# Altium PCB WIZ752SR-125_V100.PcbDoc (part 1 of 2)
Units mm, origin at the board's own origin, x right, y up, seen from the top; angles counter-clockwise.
Board outline 60 x 85 mm, 4 copper layers (Top Layer, Internal Plane 1, Internal Plane 2, Bottom Layer); 105 components, 107 nets, 391 pads, 152 vias.
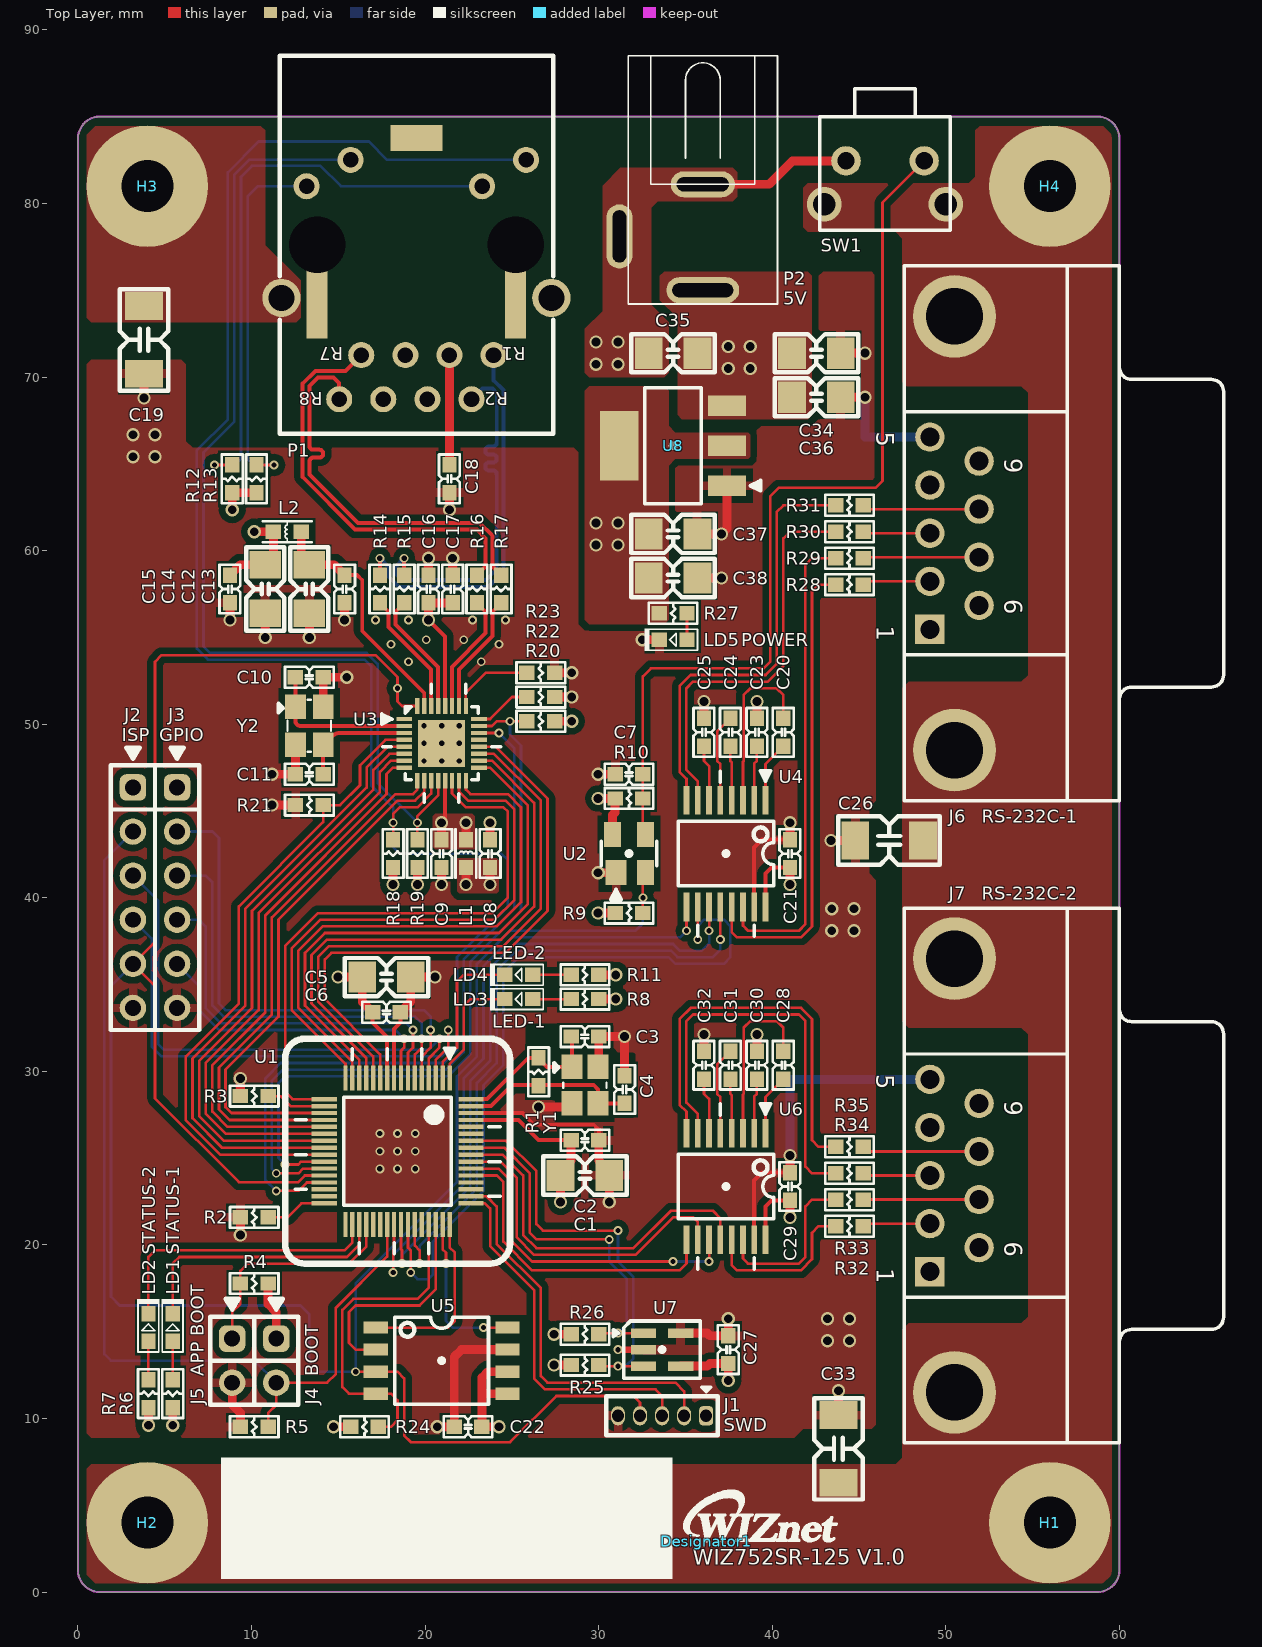
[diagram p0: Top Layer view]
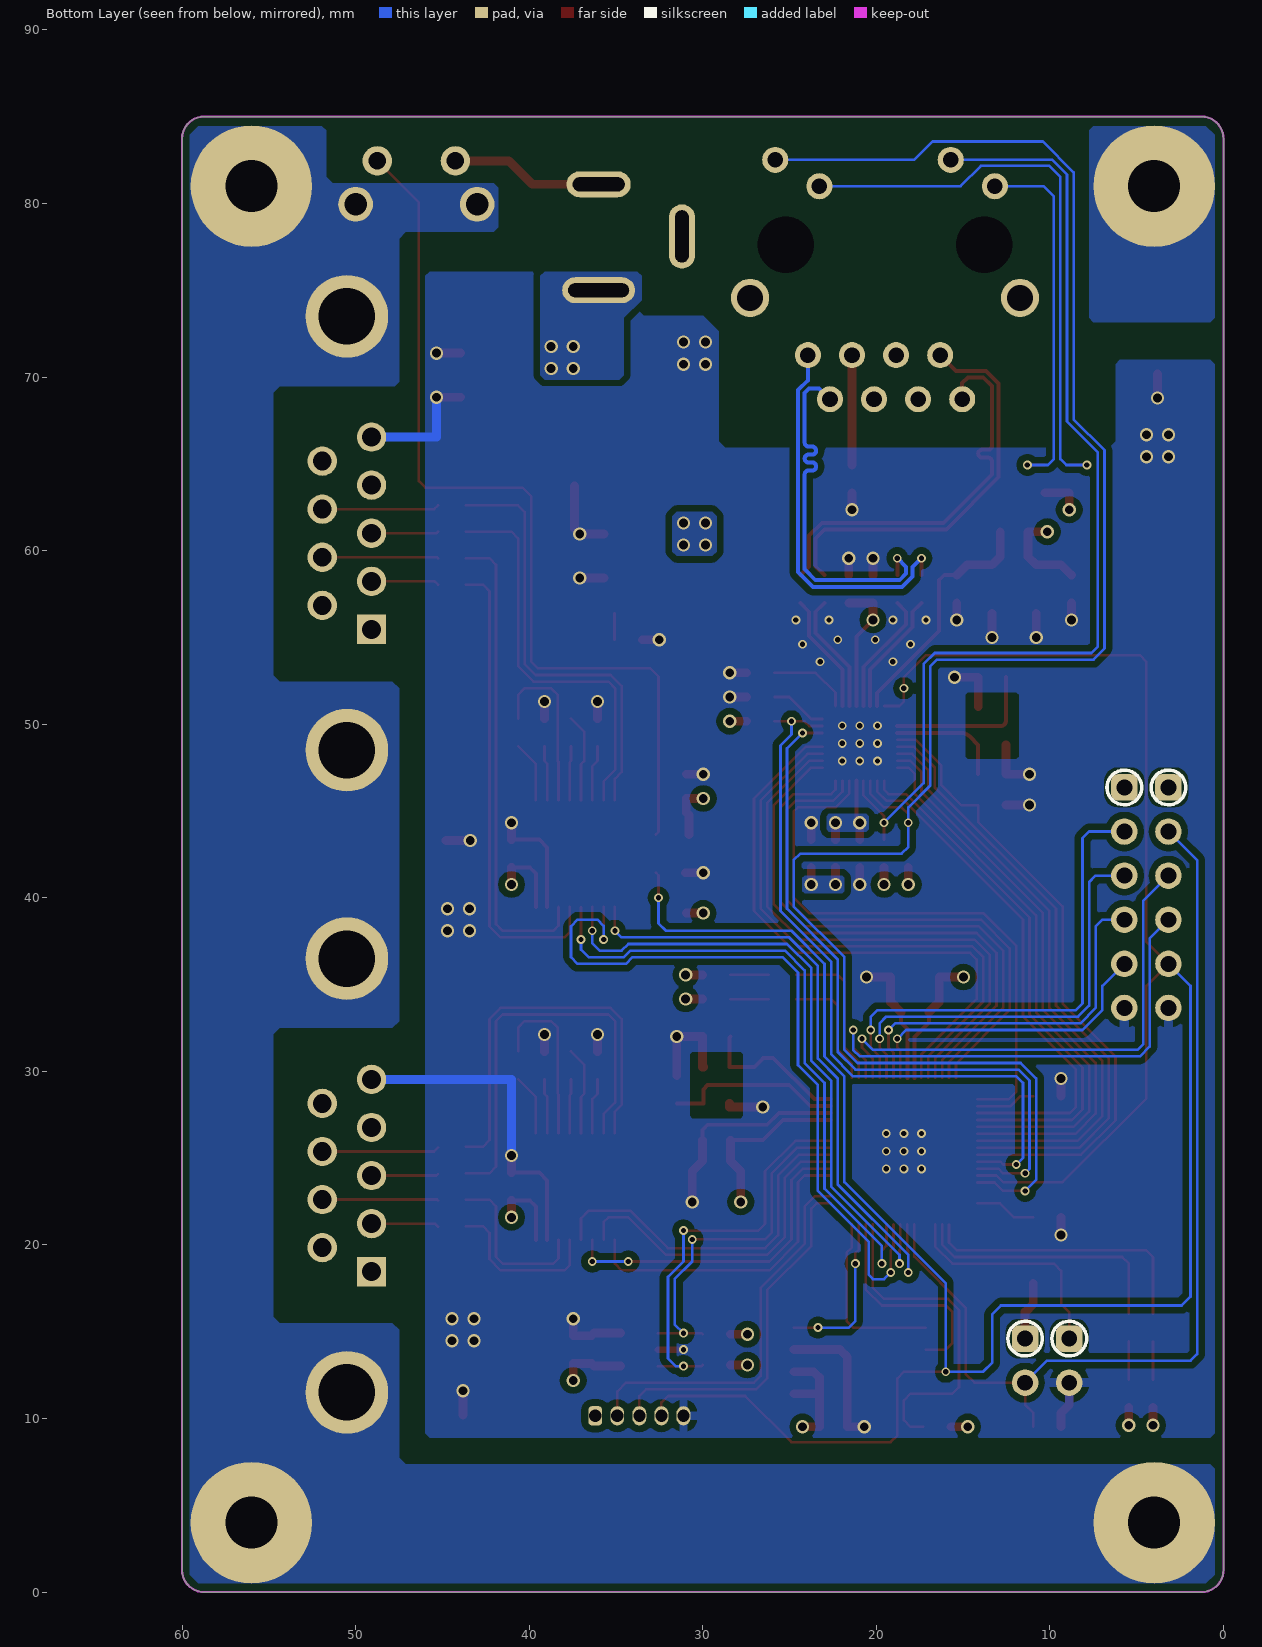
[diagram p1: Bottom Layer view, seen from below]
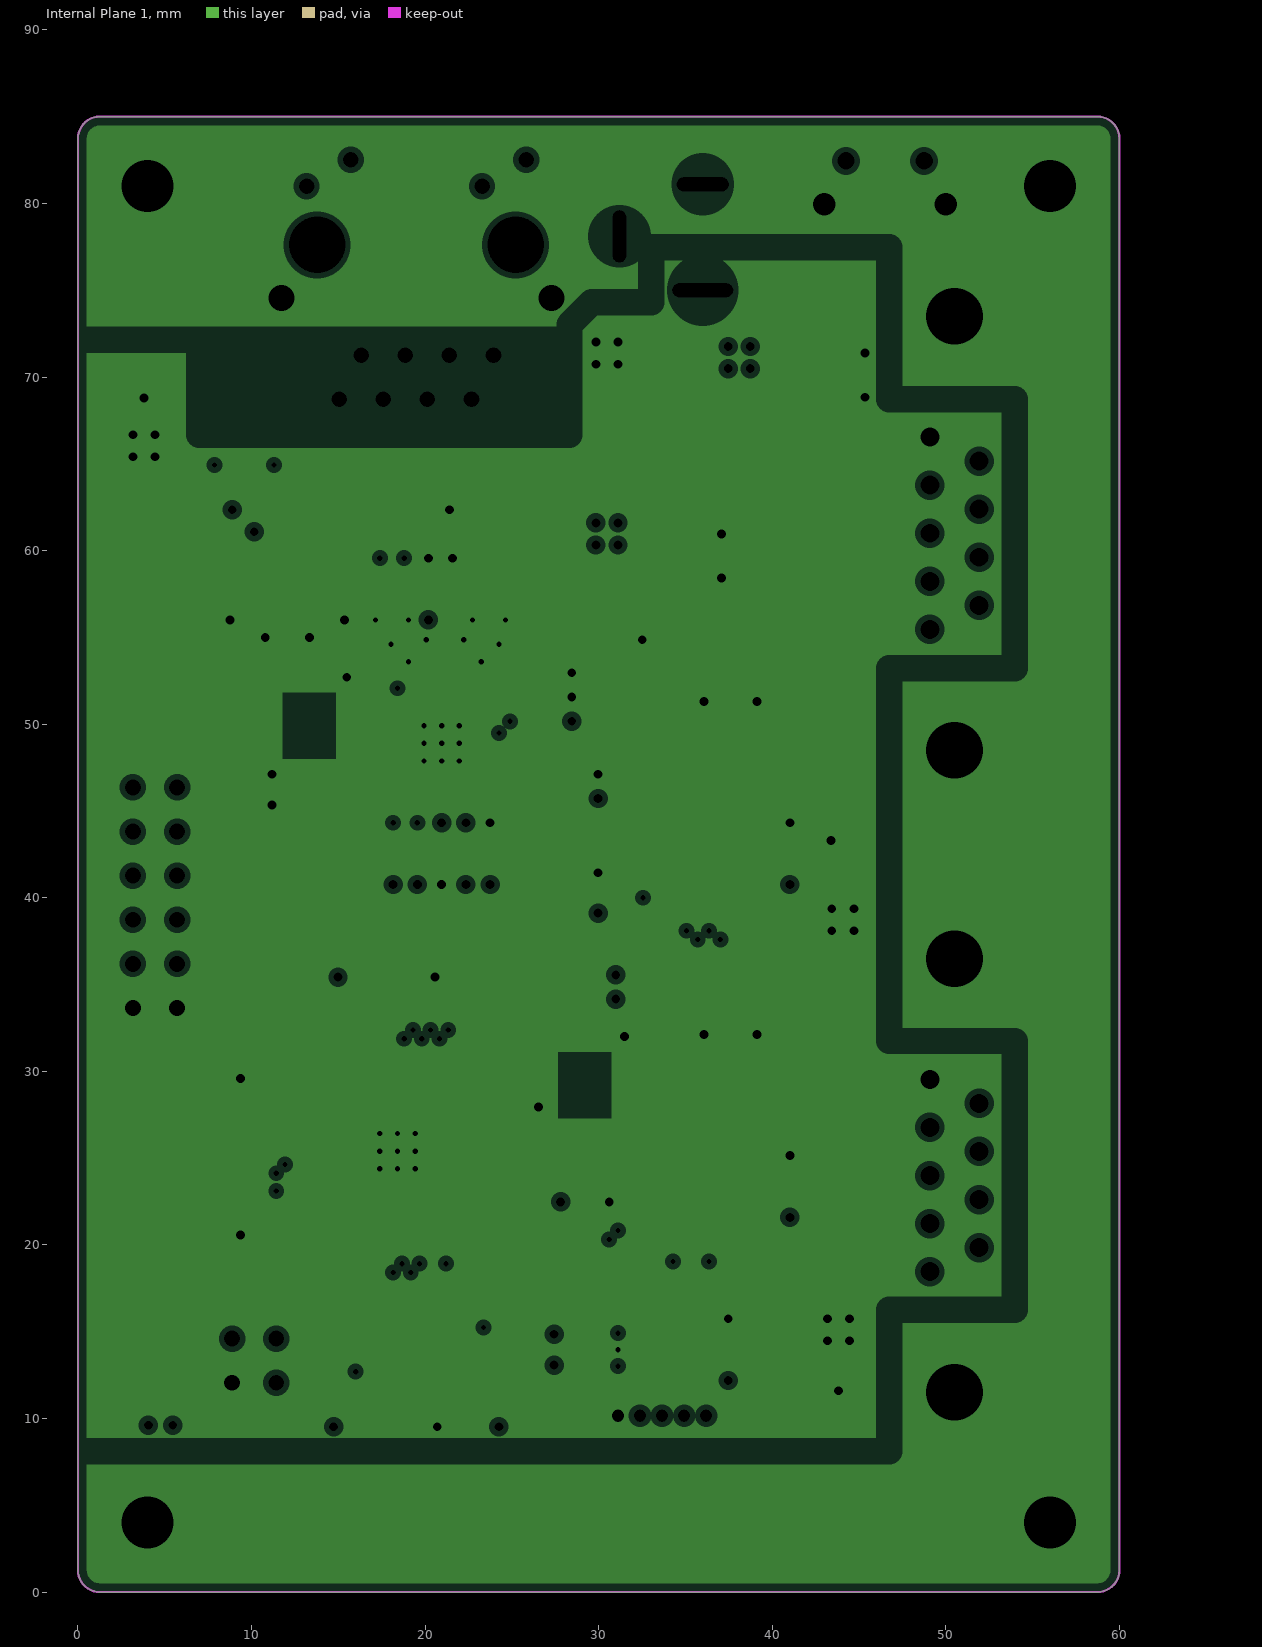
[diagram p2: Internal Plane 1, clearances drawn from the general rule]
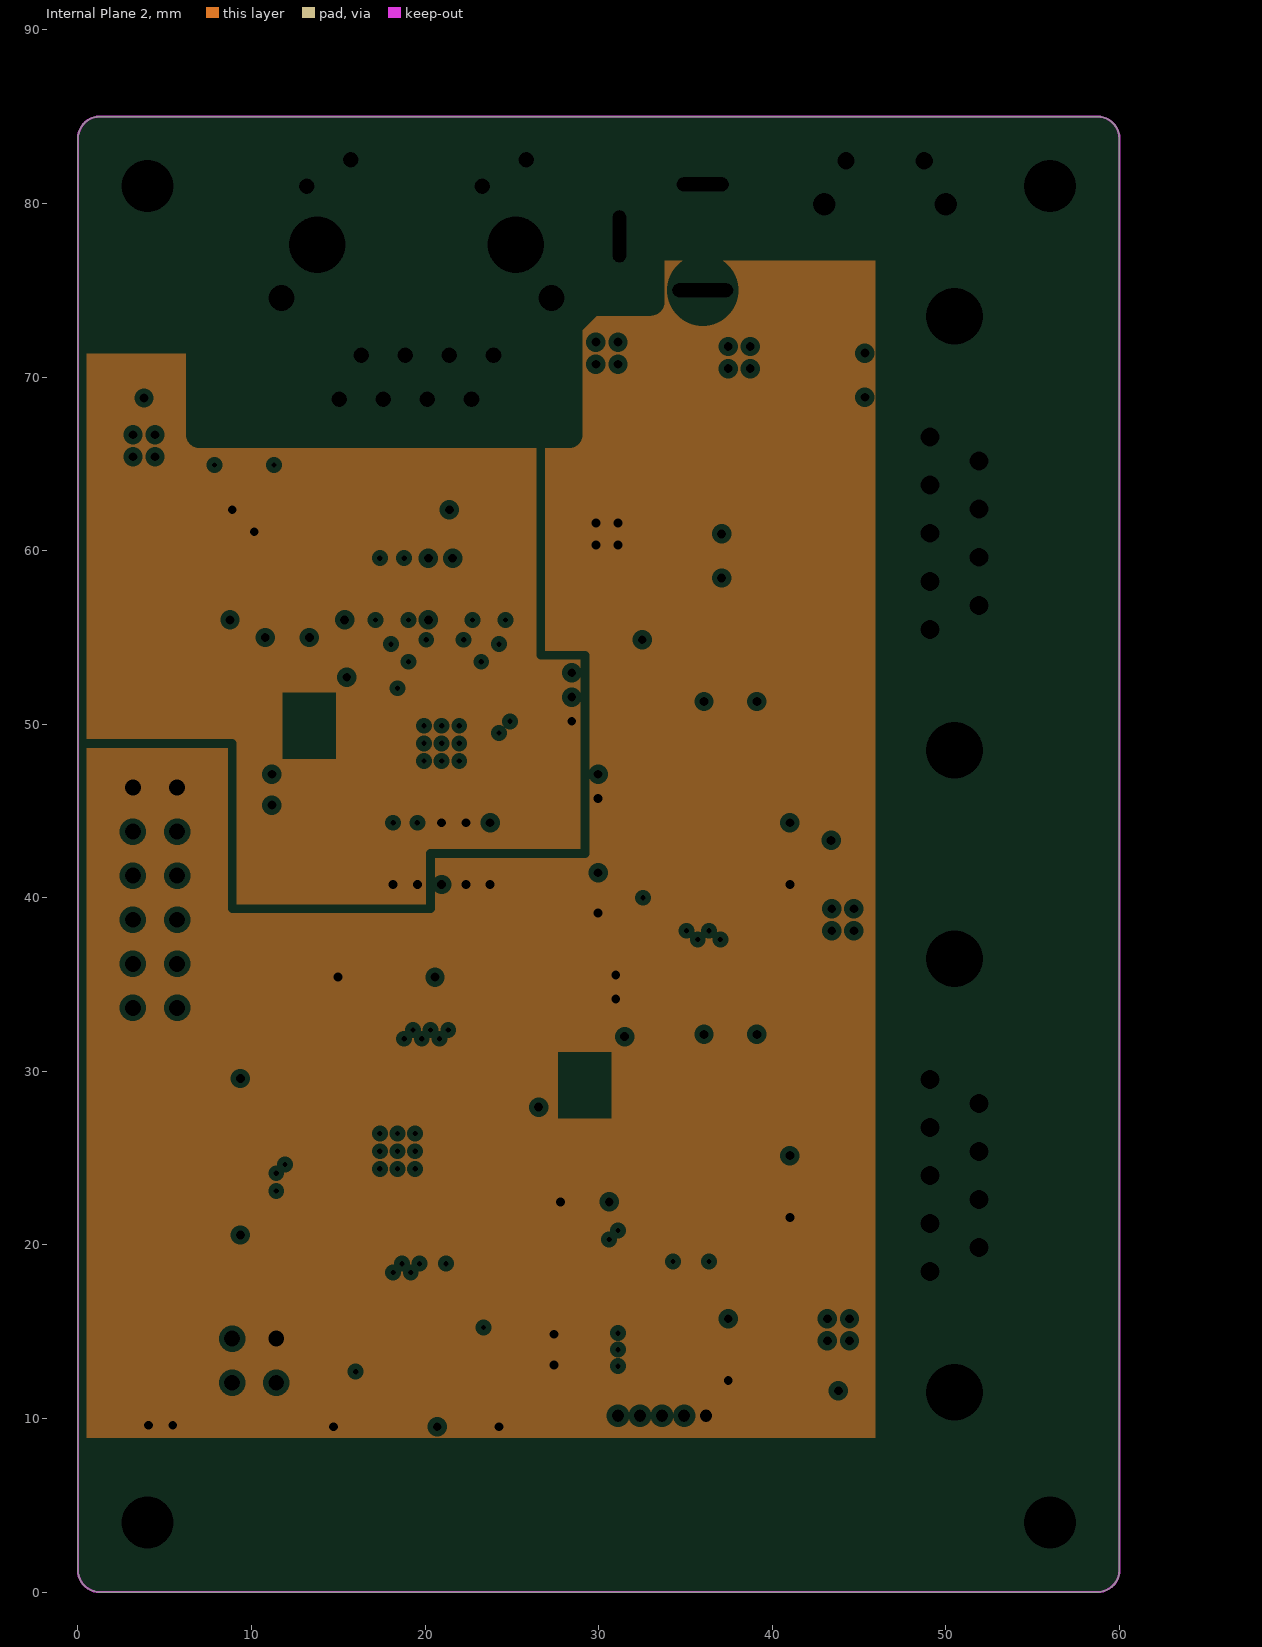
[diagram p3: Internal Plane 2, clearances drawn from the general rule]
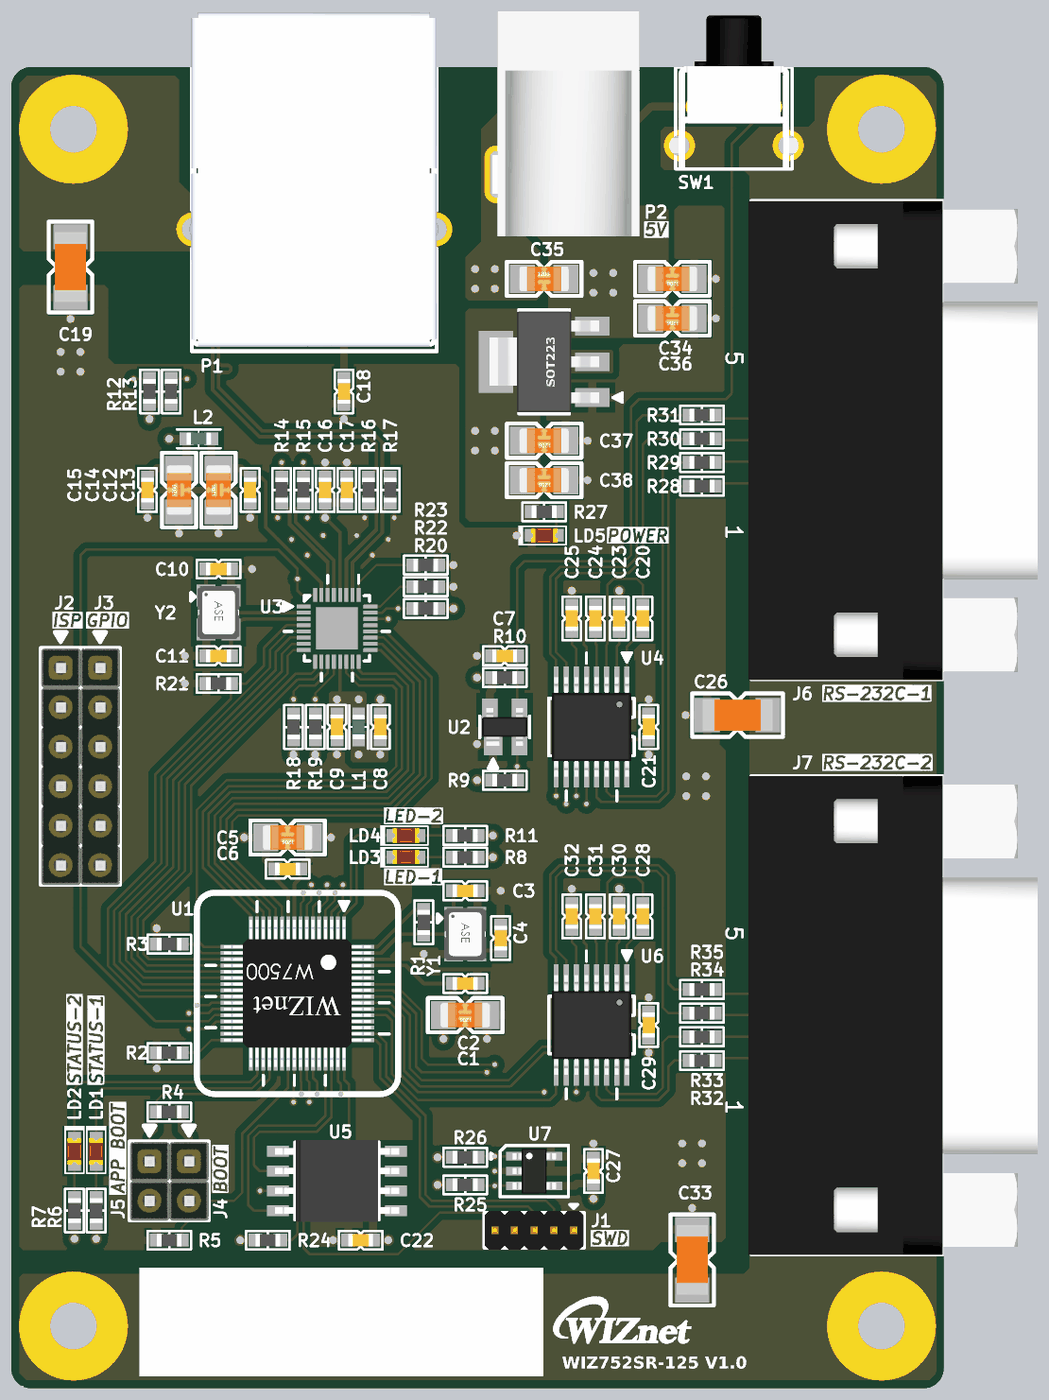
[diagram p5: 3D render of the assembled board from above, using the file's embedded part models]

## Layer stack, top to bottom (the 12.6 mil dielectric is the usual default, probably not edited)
Top Solder: solder mask 0.0102, Solder Resist, Dk 3.5
Top Layer: signal copper 0.0356
Dielectric1: core 0.32, FR-4, Dk 4.8
Internal Plane 1: plane copper 0.0356, net GND
Dielectric5: prepreg 0.32, FR-4, Dk 4.8
Internal Plane 2: plane copper 0.0356, net 3.3V
Dielectric6: core 0.32, FR-4, Dk 4.8
Bottom Layer: signal copper 0.0356
Bottom Solder: solder mask 0.0102, Solder Resist, Dk 3.5

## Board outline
0,1.27 ccw(c1.27,1.27) 1.27,0 58.73,0 ccw(c58.73,1.27) 60,1.27 60,83.73 ccw(c58.73,83.73) 58.73,85 1.27,85 ccw(c1.27,83.73) 0,83.73

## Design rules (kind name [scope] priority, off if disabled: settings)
Clearance [All] p1: gap=0.15 ignorepadtopadclearanceinfootprint=FALSE except(0: Arc-Hole Track-Hole SMDPad-Hole THPad-Hole Via-Hole Fill-Hole Poly-Hole Region-Hole Text-Hole)
DiffPairsRouting [All] p1: maxlimit=0.152 minlimit=0.152 mostfreqgap=0.152 toplayer_minwidth=0.152 toplayer_maxwidth=0.229 toplayer_prefwidth=0.152 bottomlayer_minwidth=0.152 bottomlayer_maxwidth=0.229 bottomlayer_prefwidth=0.152 maxuncoupledlength=15.24
HoleSize [All] p1: absolutevalues=TRUE maxlimit=4.064 minlimit=0.025 maxpercent=80.000 minpercent=20.000
PlaneClearance [All] p1: clearance=0.305
PlaneConnect [All] p1: planeconnectstyle=Direct reliefexpansion=0.508 reliefentries=4 reliefconductorwidth=0.254 reliefairgap=0.254
PolygonConnect PolygonConnect_2 [IsPad vs IsNamedPolygon('Top Layer-GND') Or  IsNamedPolygon('Bottom Layer-GND')] p1: connectstyle=Relief reliefconductorwidth=0.508 reliefentries=4 polygonreliefangle="90 Angle" airgapwidth=0.381
PolygonConnect PolygonConnect_1 [IsVia] p2: connectstyle=Direct reliefconductorwidth=0.254 reliefentries=4 polygonreliefangle="90 Angle" airgapwidth=0.254
PolygonConnect [All] p3: connectstyle=Direct reliefconductorwidth=0.254 reliefentries=4 polygonreliefangle="90 Angle" airgapwidth=0.254
RoutingVias [All] p1: holewidth=0.305 width=0.508 viastyle="Through Hole" minholewidth=0.305 minwidth=0.508 maxholewidth=0.508 maxwidth=0.762
SolderMaskExpansion [All] p1: expansion=0
Width [All] p1: maxlimit=2.54 minlimit=0.102 preferedwidth=0.152
26 further rules are at their usual default settings.

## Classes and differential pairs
differential pair U3-2: +NetR16_2 -NetR17_2
differential pair U3-1: +NetR14_2 -NetR15_2
differential pair MDI_R: +MDI_R_P -MDI_R_N
differential pair MDI_T: +MDI_T_P -MDI_T_N

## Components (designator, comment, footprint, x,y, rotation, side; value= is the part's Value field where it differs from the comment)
C1 "10uF" CAP-1206 29.21,24.003 r180 top
C2 "1uF" CAP-0603 29.21,26.035 r180 top
C3 "30pF" CAP-0603 29.21,32.004 r180 top
C4 "30pF" CAP-0603 31.496,28.956 r270 top
C5 "10uF" CAP-1206 17.78,35.433 r180 top
C6 "1uF" CAP-0603 17.78,33.401 r180 top
C7 "0.1uF" CAP-0603 31.75,47.117 r180 top
C8 "0.1uF" CAP-0603 23.749,42.545 r270 top
C9 "0.1uF" CAP-0603 20.955,42.545 r90 top
C10 "27pF" CAP-0603 13.335,52.705 r180 top
C11 "27pF" CAP-0603 13.335,47.117 r0 top
C12 "10uF" CAP-1206 13.335,57.785 r90 top
C13 "0.1uF" CAP-0603 15.367,57.785 r90 top
C14 "10uF" CAP-1206 10.795,57.785 r90 top
C15 "0.1uF" CAP-0603 8.763,57.785 r90 top
C16 "0.1uF" CAP-0603 20.193,57.785 r270 top
C17 "0.1uF" CAP-0603 21.59,57.785 r270 top
C18 "0.1uF" CAP-0603 21.405,64.135 r90 top locked
C19 "1nF/2kV" CAP-1808 3.81,72.136 r90 top locked
C20 "0.1uF" CAP-0603 40.64,49.53 r90 top
C21 "0.1uF" CAP-0603 41.021,42.545 r270 top
C22 "0.1uF" CAP-0603 22.479,9.525 r0 top
C23 "0.1uF" CAP-0603 39.116,49.53 r270 top
C24 "0.1uF" CAP-0603 37.592,49.53 r90 top
C25 "0.1uF" CAP-0603 36.068,49.53 r270 top
C26 "1nF/2kV" CAP-1808 46.736,43.307 r180 top
C27 "0.1uF" CAP-0603 37.465,13.97 r270 top
C28 "0.1uF" CAP-0603 40.64,30.353 r90 top
C29 "0.1uF" CAP-0603 41.021,23.368 r270 top
C30 "0.1uF" CAP-0603 39.116,30.353 r270 top
C31 "0.1uF" CAP-0603 37.592,30.353 r90 top
C32 "0.1uF" CAP-0603 36.068,30.353 r270 top
C33 "1nF/2kV" CAP-1808 43.815,8.255 r90 top
C34 "10uF" CAP-1206 42.545,71.374 r180 top
C35 "4.7uF" CAP-1206 34.29,71.374 r0 top
C36 "10uF" CAP-1206 42.545,68.834 r180 top
C37 "10uF" CAP-1206 34.29,60.96 r180 top
C38 "4.7uF" CAP-1206 34.29,58.42 r180 top
Designator1 "Comment" LOGO-WIZNET(SMALL) 36.195,2.921 r0 top locked
H1 "PCB Hole" HOLE-3.0/7.0 56,4 r90 top locked
H2 "PCB Hole" HOLE-3.0/7.0 4,4 r90 top locked
H3 "PCB Hole" HOLE-3.0/7.0 4,81 r0 top locked
H4 "PCB Hole" HOLE-3.0/7.0 56,81 r0 top locked
J1 "1.27mm 1x5 Pin Header DIP" IDC-1X5(1.27MM) 36.195,10.16 r180 top
J2 "2.54mm 1x6 Pin Header DIP" IDC-1X6 3.175,46.355 r270 top locked
J3 "2.54mm 1x6 Pin Header DIP" IDC-1X6 5.715,46.355 r270 top locked
J4 "2.54mm 1x2 Pin Header DIP" IDC-1X2 11.43,14.605 r270 top
J5 "2.54mm 1x2 Pin Header DIP" IDC-1X2 8.89,14.605 r270 top
J6 "D-SUB9-MALE" D-SUB9-MALE 60,61 r270 top locked
J7 "D-SUB9-MALE" D-SUB9-MALE 60,24 r270 top locked
L1 "HH-1M1608-121JT" IND-0603 22.352,42.545 r90 top
L2 "HH-1M1608-121JT" IND-0603 12.065,61.087 r180 top
LD1 "LED-0603" LED-0603-RED 5.461,15.24 r90 top
LD2 "LED-0603" LED-0603-RED 4.064,15.24 r90 top
LD3 "LED-0603" LED-0603-RED 25.4,34.163 r180 top
LD4 "LED-0603" LED-0603-RED 25.4,35.56 r180 top
LD5 "LED-0603" LED-0603-RED 34.29,54.864 r180 top
P1 "BS-RB10005" RJ45-RB10005 19.5,77.61 r180 top locked
P2 "DC-JACK 2pi" "DC-JACK 2pi" 36,78.1 r180 top locked
R1 "1M" RES-0603 26.543,29.972 r90 top
R2 "4.7K" RES-0603 10.16,21.59 r0 top
R3 "4.7K" RES-0603 10.16,28.575 r0 top
R4 "4.7K" RES-0603 10.16,17.78 r0 top
R5 "4.7K" RES-0603 10.16,9.525 r0 top
R6 "330R" RES-0603 5.461,11.43 r270 top
R7 "330R" RES-0603 4.064,11.43 r270 top
R8 "330R" RES-0603 29.21,34.163 r0 top
R9 "4.7K" RES-0603 31.75,39.116 r180 top
R10 "4.7K" RES-0603 31.75,45.72 r180 top
R11 "330R" RES-0603 29.21,35.56 r0 top
R12 "330R" RES-0603 8.89,64.135 r90 top
R13 "330R" RES-0603 10.287,64.135 r90 top
R14 "33R" RES-0603 17.399,57.785 r270 top
R15 "33R" RES-0603 18.796,57.785 r270 top
R16 "33R" RES-0603 22.987,57.785 r270 top
R17 "33R" RES-0603 24.384,57.785 r270 top
R18 "5.1K" RES-0603 18.161,42.545 r270 top
R19 "5.1K" RES-0603 19.558,42.545 r270 top
R20 "5.1K" RES-0603 26.67,50.165 r0 top
R21 "5.1K" RES-0603 13.335,45.339 r180 top
R22 "5.1K" RES-0603 26.67,51.562 r0 top
R23 "6.19K" RES-0603 26.67,52.959 r0 top
R24 "4.7K" RES-0603 16.51,9.525 r180 top
R25 "4.7K" RES-0603 29.21,13.081 r180 top
R26 "4.7K" RES-0603 29.21,14.859 r180 top
R27 "330R" RES-0603 34.29,56.388 r180 top
R28 "33R" RES-0603 44.45,58.039 r0 top
R29 "33R" RES-0603 44.45,59.563 r0 top
R30 "33R" RES-0603 44.45,61.087 r0 top
R31 "33R" RES-0603 44.45,62.611 r0 top
R32 "33R" RES-0603 44.45,21.082 r0 top
R33 "33R" RES-0603 44.45,22.606 r0 top
R34 "33R" RES-0603 44.45,24.13 r0 top
R35 "33R" RES-0603 44.45,25.654 r0 top
SW1 "IT-1102VA" IT-1102VA 46.5,82.45 r180 top
U1 "W7500" W7500-LQFP64 18.415,25.4 r270 top locked
U2 "MIC811SUY" SOT-143 31.75,42.545 r0 top
U3 "IP101GR/GRI" QFN32(0.4/4X4) 20.955,48.895 r0 top locked
U4 "SP3232EBEY" TSSOP16(0.65/6.4) 37.338,42.545 r270 top
U5 "AT45DB161E-SHF-T" SO-08-EIAJ 20.955,13.335 r0 top
U6 "SP3232EBEY" TSSOP16(0.65/6.4) 37.338,23.368 r270 top
U7 "24AA16T-I/OT" SOT-23-5L 33.655,13.97 r0 top
U8 "AME8815BEGT330Z" SOT-223 34.29,66.04 r90 top
Y1 "12MHz" OSC-TZ1067B 29.21,29.21 r270 top
Y2 "25MHz" OSC-82J0626 13.335,49.911 r270 top

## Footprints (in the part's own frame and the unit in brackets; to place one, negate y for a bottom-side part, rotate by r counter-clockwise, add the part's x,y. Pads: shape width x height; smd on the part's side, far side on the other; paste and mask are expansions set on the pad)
CAP-0603 [mm] "Ceramic CAP 0603(1608)"
  rect 0.89x0.82 smd: 1(-0.8,0) 2(0.8,0)
  silkscreen extent -1.4,-0.6 1.4,0.6, body extent -0.93,-0.41 0.93,0.41, height 0.81
CAP-1206 [mm]
  rect 1.6x1.8 smd: 1(-1.4,0) 2(1.4,0)
  silkscreen extent -2.4,-1.1 2.4,1.1, body extent -1.6,-0.8 1.6,0.8, height 1
CAP-1808 [mm] "Ceramic CAP 1808(4520)"
  rect 1.6x2.2 smd: 1(-1.95,0) 2(1.95,0)
  silkscreen extent -2.92,-1.4 2.92,1.4, body extent -2.25,-1.02 2.25,1.01, height 2
D-SUB9-MALE [mm] "D-SUB9, MALE, Right Angle;"
  rect 1.69x1.69 hole 1.09: 1(5.54,-10.92)
  round 1.69 hole 1.09: 2(2.77,-10.92) 3(0,-10.92) 4(-2.77,-10.92) 5(-5.54,-10.92) 6(4.155,-8.08) 7(1.385,-8.08) 8(-1.385,-8.08) 9(-4.155,-8.08)
  round 4.76 hole 3.26: 10(-12.495,-9.5) 11(12.495,-9.5)
  silkscreen extent -15.4,-12.4 15.4,6, body extent -15.38,-12.55 15.43,6.05, height 12.57
"DC-JACK 2pi" [mm] "DC-JACK 2pi"
  oval 4.2x1.5 hole 0.8 slot 3.5 at 0 deg: 1(0,3.1)
  oval 1.5x3.7 hole 0.8 slot 3 at 90 deg: 2(4.8,0)
  oval 3.7x1.5 hole 0.8 slot 3 at 0 deg: 3(0,-3)
  silkscreen extent -4.3,-10.4 4.3,3.9, body extent -4.42,-10.49 5.05,3.99, height 11.18
HOLE-3.0/7.0 [mm]
  round 7 hole 3: 1(0,0)
IDC-1X2 [mil]
  rrect50% 60x60 hole 36: 1(0,0)
  round 60 hole 36: 2(100,0)
  silkscreen extent -90,-50 150,50, body extent -49,-49 151,51, height 336
IDC-1X5(1.27MM) [mm]
  rrect50% 0.8x1.1 hole 0.7: 1(0,0)
  oval 0.8x1.1 hole 0.7: 2(1.27,0) 3(2.54,0) 4(3.81,0) 5(5.08,0)
  silkscreen extent -0.66,-1.65 5.74,1.11, body extent -0.63,-1.25 5.72,1.25, height 6.5
IDC-1X6 [mil] "6-Way 2.54 mm Male Header"
  rrect50% 60x60 hole 36: 1(0,0)
  round 60 hole 36: 2(100,0) 3(200,0) 4(300,0) 5(400,0) 6(500,0)
  silkscreen extent -90,-50 550,50, body extent -49,-49 551,51, height 336
IND-0603 [mm] "Inductor 0603(1608)"
  rect 0.89x0.82 smd: 1(-0.8,0) 2(0.8,0)
  Top Layer pour cut-out: -0.254,0.508 -0.254,-0.508 0.254,-0.508 0.254,0.508
  silkscreen extent -1.4,-0.6 1.4,0.6, body extent -0.8,-0.4 0.8,0.4, height 0.95
IT-1102VA [mm]
  round 1.7 hole 1: 1(-2.25,0) 2(2.25,0)
  round 2 hole 1.3: 3(-3.5,2.5) 4(3.5,2.5)
  silkscreen extent -3.75,-4.15 3.75,4, body extent -4.2,-5.86 4.2,4, height 7.06
LED-0603-RED [mm] "LED-0603-RED"
  rect 0.89x0.82 smd: 1(-0.8,0) 2(0.8,0)
  silkscreen extent -1.41,-0.65 1.65,0.65, body extent -0.85,-0.45 0.85,0.45, height 0.9
LOGO-WIZNET(SMALL) [mm]
  silkscreen extent -1.27,0 7.52,2.93
OSC-82J0626 [mm]
  rect 1.4x1.2 smd: 1(-1.1,-0.8) 2(1.1,-0.8) 3(1.1,0.8) 4(-1.1,0.8)
  silkscreen extent -1.5,-1.78 1.5,1.25, body extent -1.7,-1.35 1.7,1.35, height 1.06
OSC-TZ1067B [mm]
  rect 1.4x1.2 smd: 1(-1.05,-0.75) 2(1.05,-0.75) 3(1.05,0.75) 4(-1.05,0.75)
  silkscreen extent -1.27,-1.78 0.15,1.25, body extent -1.7,-1.35 1.7,1.35, height 1.06
QFN32(0.4/4X4) [mm]
  rect 0.9x0.25 smd: 1(-2.15,1.4) 2(-2.15,1) 3(-2.15,0.6) 4(-2.15,0.2) 5(-2.15,-0.2) 6(-2.15,-0.6) 7(-2.15,-1) 8(-2.15,-1.4) 17(2.15,-1.4) 18(2.15,-1) 19(2.15,-0.6) 20(2.15,-0.2) 21(2.15,0.2) 22(2.15,0.6) 23(2.15,1) 24(2.15,1.4)
  rect 0.25x0.9 smd: 9(-1.4,-2.15) 10(-1,-2.15) 11(-0.6,-2.15) 12(-0.2,-2.15) 13(0.2,-2.15) 14(0.6,-2.15) 15(1,-2.15) 16(1.4,-2.15) 25(1.4,2.15) 26(1,2.15) 27(0.6,2.15) 28(0.2,2.15) 29(-0.2,2.15) 30(-0.6,2.15) 31(-1,2.15) 32(-1.4,2.15)
  rect 2.7x2.7 smd: 33(0,0)
  silkscreen extent -3.45,-3.4 3.4,3.4, body extent -2.1,-2.1 2.1,2.1, height 0.76
RES-0603 [mm] "RES-0603"
  rect 0.89x0.82 smd: 1(-0.8,0) 2(0.8,0)
  silkscreen extent -1.4,-0.6 1.4,0.6, body extent -0.82,-0.41 0.82,0.41, height 0.46
RJ45-RB10005 [mm]
  round 2.2 hole 1.5: 0(-7.775,3.05) 0(7.775,3.05)
  round 1.5 hole 0.9: L1(6.325,-3.38) L2(3.785,-4.9) L3(-3.785,-3.38) L4(-6.325,-4.9) R1(-4.445,6.35) R2(-3.175,8.89) R3(-1.905,6.35) R4(-0.635,8.89) R5(0.635,6.35) R6(1.905,8.89) R7(3.175,6.35) R8(4.445,8.89)
  rect 1.2x4.7 smd: ""(-5.715,3.05) ""(5.715,3.05)
  round 3 hole 3.25 unplated paste+0 mask+0.102: ""(-5.715,0) ""(5.715,0)
  rect 3x1.5 smd: ""(0,-6.15)
  silkscreen extent -7.88,-10.89 7.88,10.89, body extent -7.97,-10.9 8.03,10.6, height 12.67
SO-08-EIAJ [mm]
  rect 1.4x0.7 smd: 1(-3.8,1.905) 2(-3.8,0.635) 3(-3.8,-0.635) 4(-3.8,-1.905) 5(3.8,-1.905) 6(3.8,-0.635) 7(3.8,0.635) 8(3.8,1.905)
  silkscreen extent -2.7,-2.5 2.7,2.5, body extent -4,-2.62 4,2.63, height 2.58
SOT-23-5L [mm]
  rect 1.45x0.55 smd: 1(-1.075,0.95) 2(-1.075,0) 3(-1.075,-0.95) 4(1.075,-0.95) 5(1.075,0.95)
  silkscreen extent -2.8,-1.65 2.2,1.65, body extent -1.4,-1.45 1.4,1.45, height 1.45
SOT-143 [mm]
  rect 1.2x1.44 smd: 1(-0.75,-1.1)
  rect 1x1.44 smd: 2(0.95,-1.1) 3(0.95,1.1) 4(-0.95,1.1)
  silkscreen extent -1.6,-2.65 1.6,0.7, body extent -1.46,-1.21 1.46,1.21, height 1
SOT-223 [mm]
  rect 1.2x2.2 smd: 1(-2.3,-3.1) 2(0,-3.1) 3(2.3,-3.1)
  rect 4x2.2 smd: 4(0,3.1)
  silkscreen extent -3.35,-5.03 3.35,1.63, body extent -3.25,-3.53 3.25,3.52, height 1.82
TSSOP16(0.65/6.4) [mil]
  rect 65x13 smd: 1(-121.04,89.57) 2(-121.04,63.98) 3(-121.04,38.39) 4(-121.04,12.8) 5(-121.04,-12.8) 6(-121.04,-38.39) 7(-121.04,-63.98) 8(-121.04,-89.57) 9(121.04,-89.57) 10(121.04,-63.98) 11(121.04,-38.39) 12(121.04,-12.8) 13(121.04,12.8) 14(121.04,38.39) 15(121.04,63.98) 16(121.04,89.57)
  silkscreen extent -188,-108 187,108, body extent -126,-100 126,100, height 47
W7500-LQFP64 [mm] "WIZnet ARM Cortex-M0, LQFP64, Pitch 0.40mm"
  rect 1.45x0.25 smd: 1(-4.225,3) 2(-4.225,2.6) 3(-4.225,2.2) 4(-4.225,1.8) 5(-4.225,1.4) 6(-4.225,1) 7(-4.225,0.6) 8(-4.225,0.2) 9(-4.225,-0.2) 10(-4.225,-0.6) 11(-4.225,-1) 12(-4.225,-1.4) 13(-4.225,-1.8) 14(-4.225,-2.2) 15(-4.225,-2.6) 16(-4.225,-3) 33(4.225,-3) 34(4.225,-2.6) 35(4.225,-2.2) 36(4.225,-1.8) 37(4.225,-1.4) 38(4.225,-1) 39(4.225,-0.6) 40(4.225,-0.2) 41(4.225,0.2) 42(4.225,0.6) 43(4.225,1) 44(4.225,1.4) 45(4.225,1.8) 46(4.225,2.2) 47(4.225,2.6) 48(4.225,3)
  rect 0.25x1.45 smd: 17(-3,-4.225) 18(-2.6,-4.225) 19(-2.2,-4.225) 20(-1.8,-4.225) 21(-1.4,-4.225) 22(-1,-4.225) 23(-0.6,-4.225) 24(-0.2,-4.225) 25(0.2,-4.225) 26(0.6,-4.225) 27(1,-4.225) 28(1.4,-4.225) 29(1.8,-4.225) 30(2.2,-4.225) 31(2.6,-4.225) 32(3,-4.225) 49(3,4.225) 50(2.6,4.225) 51(2.2,4.225) 52(1.8,4.225) 53(1.4,4.225) 54(1,4.225) 55(0.6,4.225) 56(0.2,4.225) 57(-0.2,4.225) 58(-0.6,4.225) 59(-1,4.225) 60(-1.4,4.225) 61(-1.8,4.225) 62(-2.2,4.225) 63(-2.6,4.225) 64(-3,4.225)
  silkscreen extent -6.48,-6.48 6.48,6.48, body extent -4.73,-4.74 4.73,4.72, height 1

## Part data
C1 C5 C12 C14 C34 C35 C36 C37 C38: library part CAP-1206, "Ceramic CAP 1206(3216)"
C2 C3 C4 C6 C7 C8 C9 C10 C11 C13 C15 C16 C17 C18 C20 C21 C22 C23 C24 C25 C27 C28 C29 C30 C31 C32: library part CAP-0603, "Ceramic CAP 0603(1608)"
C19 C26 C33: library part CAP-1808, "Ceramic CAP 1808(4520)"
H1 H2 H3 H4: "PCB Supporter Hole"
J6 J7: "D-SUB-9, MALE,  Right Angle"
L1 L2: library part IND-0603, "Inductor 0603(1608)"
P1: library part RB1-125BAG1A, "10/100 BASE-TX MAGJACK"
R1 R2 R3 R4 R5 R6 R7 R8 R9 R10 R11 R12 R13 R14 R15 R16 R17 R18 R19 R20 R21 R22 R23 R24 R25 R26 R27 R28 R29 R30 R31 R32 R33 R34 R35: library part RES-0603, "RES0603"
SW1: "IT-1102VA-3.85MM"
U1: "WIZnet ARM Cortex-M0"
U2: "Microprocessor Reset Circuits"
U4 U6: "True +3.0V to +5.5V RS-232 Transceivers"
U5: "16-Mbit DataFlash, 2.3V or 2.5V Minimum SPI Serial Flash Memory"
U7: library part 24AAxxT-i-OT, "SOT-23"
U8: "1.5A CMOS LDO"
Y1: library part OSC-TZ1067B-12MHz, "X-tal 12MHz,3.2x2.5 SMD, CL=20pF"
Y2: library part OSC-82J0626-25MHz, "X-tal 25MHz,3.2x2.5 SMD, CL=18pF"

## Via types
v1: diameter 0.762, hole 0.508, Top Layer to Bottom Layer, tented both sides, 87 vias
v2: diameter 0.508, hole 0.305, Top Layer to Bottom Layer, tented both sides, 65 vias

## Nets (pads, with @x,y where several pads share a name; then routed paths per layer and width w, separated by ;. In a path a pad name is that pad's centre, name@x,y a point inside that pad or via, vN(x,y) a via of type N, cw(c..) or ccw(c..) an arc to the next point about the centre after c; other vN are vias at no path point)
3.3V: C1.2 C2.2 C5.2 C6.2 C8.2 C21.2 C22.2 C27.2 C29.2 C37.2 C38.2 J1.1 J2.1 J3.1 J4.1 L1.1 R4.2 R6.2 R7.2 R8.2 R9.2 R10.2 R11.2 R24.2 R25.2 R26.2 R27.2 U1.10 U1.61 U2.4 U4.16 U5.5 U5.6 U6.16 U7.4 U8.2 U8.4 | length 53.8
  Top Layer w0.229: C6.2@16.98,33.401 16.98,32.804 17.815,31.969 U1.10@17.815,29.625 ; U1.61@22.64,27.2 25.378,27.2 26.543,26.035 C2.2@28.41,26.035 ; U6.16@39.613,20.294 39.613,22.214 39.967,22.568 C29.2@41.021,22.568 ; U4.16@39.613,39.471 39.613,41.391 39.967,41.745 C21.2@41.021,41.745
  Top Layer w0.508: v1(4.064,9.614) R7.2@4.064,10.63 ; v1(5.461,9.614) R6.2@5.461,10.63 ; R4.2@10.96,17.78 10.96,16.599 11.43,16.129 J4.1@11.43,14.605 ; v1(14.732,9.525) R24.2@15.71,9.525 ; v1(14.986,35.433) C5.2@16.38,35.433 16.38,34.001 C6.2@16.98,33.401 ; v1(22.352,40.767) L1.1@22.352,41.745 ; 23.298,11.43 U5.5@24.755,11.43 ; v1(23.749,40.767) C8.2@23.749,41.745 ; v1(24.257,9.525) C22.2@23.279,9.525 23.279,12.357 23.622,12.7 U5.6@24.755,12.7 ; v1(27.432,13.081) R25.2@28.41,13.081 ; v1(27.432,14.859) R26.2@28.41,14.859 ; v1(27.81,22.479) C1.2@27.81,24.003 27.81,24.254 28.41,24.854 C2.2@28.41,26.035 ; v1(29.972,39.116) R9.2@30.95,39.116 ; v1(29.972,45.72) R10.2@30.95,45.72 30.95,44.92 30.8,44.77 U2.4@30.8,43.645 ; R8.2@30.01,34.163 v1(30.988,34.163) ; R11.2@30.01,35.56 v1(30.988,35.56) ; U7.4@34.73,13.02 36.261,13.02 36.411,13.17 C27.2@37.465,13.17 v1(37.465,12.192) ; v1(41.021,21.59) C29.2@41.021,22.568 ; v1(41.021,40.767) C21.2@41.021,41.745
  other v1: 29.845,60.325 31.115,60.325 29.845,61.595 31.115,61.595
5V: C34.2 C35.2 C36.2 P2.1 U8.3
  other v1: 37.465,70.485 38.735,70.485 37.465,71.755 38.735,71.755
APP_BOOT: J5.1 R4.1 U1.36 | length 13.2
  Top Layer w0.152: J5.1@8.89,14.605 8.89,16.129 9.36,16.599 R4.1@9.36,17.78 9.36,18.504 9.779,18.923 15.621,18.923 16.615,19.917 U1.36@16.615,21.175
BOOT: J2.2 J4.2 R5.2 U1.39 | length 57.6
  Top Layer w0.152: R5.2@10.96,9.525 10.96,10.325 11.43,10.795 J4.2@11.43,12.065 14.351,12.065 14.859,12.573 14.859,16.383 17.815,19.339 U1.39@17.815,21.175
  Bottom Layer w0.152: J2.2@3.175,43.815 1.524,42.164 1.524,13.716 1.905,13.335 10.16,13.335 J4.2@11.43,12.065
CH_GND: C19.2 C26.1 C33.1 H1.1 H2.1 H3.1 H4.1 J6.10 J6.11 J7.10 J7.11 P1.0 SW1.3 SW1.4
COL: R21.1 U1.25 U3.4 | length 37.1
  Top Layer w0.152: U1.25@14.19,25.2 8.201,25.2 6.223,27.178 6.223,30.861 9.271,33.909 9.271,39.497 14.135,44.361 R21.1@14.135,45.339 15.113,45.339 16.256,46.482 16.256,47.625 17.726,49.095 U3.4@18.805,49.095
CRS: U1.11 U3.20 | length 33.8
  Top Layer w0.152: U1.11@17.415,29.625 17.415,30.972 14.224,34.163 14.224,36.449 14.605,36.83 24.638,36.83 27.051,39.243 27.051,45.72 24.076,48.695 U3.20@23.105,48.695
EX_GPIO_A: J3.5 U1.8 | length 18
  Top Layer w0.152: U1.8@18.615,29.625 18.615,31.188 18.796,31.369 v2(18.796,31.877)
  Bottom Layer w0.152: J3.5@5.715,36.195 6.985,34.925 6.985,33.528 8.128,32.385 18.288,32.385 v2(18.796,31.877)
EX_GPIO_B: J3.4 U1.7 | length 21.9
  Top Layer w0.152: U1.7@19.015,29.625 19.015,31.08 19.304,31.369 v2(19.304,32.385)
  Bottom Layer w0.152: J3.4@5.715,38.735 6.985,38.735 7.366,38.354 7.366,33.655 8.255,32.766 18.923,32.766 v2(19.304,32.385)
EX_GPIO_C: J3.3 U1.6 | length 25.1
  Top Layer w0.152: U1.6@19.415,29.625 19.415,30.972 19.812,31.369 v2(19.812,31.877)
  Bottom Layer w0.152: J3.3@5.715,41.275 7.366,41.275 7.747,40.894 7.747,33.782 8.382,33.147 19.431,33.147 19.812,32.766 v2(19.812,31.877)
EX_GPIO_D: J3.2 U1.5 | length 28.3
  Top Layer w0.152: U1.5@19.815,29.625 19.815,30.864 20.32,31.369 v2(20.32,32.385)
  Bottom Layer w0.152: J3.2@5.715,43.815 7.747,43.815 8.128,43.434 8.128,33.909 8.509,33.528 19.939,33.528 20.32,33.147 v2(20.32,32.385)
GND: C1.1 C2.1 C3.1 C4.1 C5.1 C6.1 C7.2 C8.1 C9.1 C10.1 C11.1 C12.1 C13.1 C14.1 C15.1 C16.1 C17.1 C18.1 C19.1 C21.1 C22.1 C23.1 C25.1 C26.2 C27.1 C29.1 C30.1 C32.1 C33.2 C34.1 C35.1 C36.1 C37.1 C38.1 J1.5 J2.6 J3.6 J5.2 J6.5 J7.5 LD5.2 P2.2 P2.3 R2.1 R3.1 R5.1 R21.2 R22.2 R23.2 SW1.2 U1.9 U1.62 U2.1 U3.33 U4.15 U5.7 U6.15 U7.2 U7.5 U8.1 Y1.2 Y1.4 Y2.2 Y2.4 | length 124.9
  Top Layer w0.229: U1.9@18.215,29.625 18.215,32.439 18.58,32.804 C6.1@18.58,33.401 ; U1.62@22.64,27.6 25.613,27.6 26.289,26.924 29.718,26.924 30.01,26.632 C2.1@30.01,26.035 ; U6.15@38.963,20.294 38.963,23.723 39.408,24.168 C29.1@41.021,24.168 ; U4.15@38.963,39.471 38.963,42.9 39.408,43.345 C21.1@41.021,43.345
  Top Layer w0.381: v2(31.115,13.97) U7.2@32.58,13.97
  Top Layer w0.508: v1(3.81,68.792) C19.1@3.81,70.186 ; v1(8.763,56.007) C15.1@8.763,56.985 ; J5.2@8.89,12.065 8.89,10.795 9.36,10.325 R5.1@9.36,9.525 ; v1(9.36,20.574) R2.1@9.36,21.59 ; R3.1@9.36,28.575 v1(9.36,29.591) ; v1(10.795,54.991) C14.1@10.795,56.385 ; v1(11.176,45.339) R21.2@12.535,45.339 ; v1(11.176,47.117) C11.1@12.535,47.117 Y2.2@12.535,48.811 ; v1(13.335,54.991) C12.1@13.335,56.385 ; Y2.4@14.135,51.011 C10.1@14.135,52.705 v1(15.494,52.705) ; v1(15.367,56.007) C13.1@15.367,56.985 ; C6.1@18.58,33.401 19.18,34.001 C5.1@19.18,35.433 v1(20.574,35.433) ; C16.1@20.193,58.585 v1(20.193,59.563) ; v1(20.701,9.525) C22.1@21.679,9.525 21.679,13.551 22.098,13.97 U5.7@24.755,13.97 ; v1(20.955,40.767) C9.1@20.955,41.745 ; v1(21.405,62.357) C18.1@21.405,63.335 ; C17.1@21.59,58.585 v1(21.59,59.563) ; C8.1@23.749,43.345 v1(23.749,44.323) ; v1(26.543,27.94) 28.46,27.94 Y1.2@28.46,28.16 ; R22.2@27.47,51.562 v1(28.448,51.562) ; R23.2@27.47,52.959 v1(28.448,52.959) ; Y1.4@29.96,30.26 30.01,30.26 C3.1@30.01,32.004 v1(31.496,32.004) C4.1@31.496,29.756 ; v1(29.972,41.445) U2.1@31,41.445 ; v1(29.972,47.117) C7.2@30.95,47.117 ; C2.1@30.01,26.035 30.01,24.854 30.61,24.254 C1.1@30.61,24.003 v1(30.61,22.479) ; v1(32.512,54.864) LD5.2@33.49,54.864 ; U7.5@34.73,14.92 36.261,14.92 36.411,14.77 C27.1@37.465,14.77 v1(37.465,15.748) ; C38.1@35.69,58.42 v1(37.084,58.42) ; C37.1@35.69,60.96 v1(37.084,60.96) 37.39,61.266 U8.1@37.39,63.74 ; P2.3@36,81.1 39.825,81.1 41.175,82.45 SW1.2@44.25,82.45 ; C32.1@36.068,31.153 v1(36.068,32.131) ; C25.1@36.068,50.33 v1(36.068,51.308) ; C30.1@39.116,31.153 v1(39.116,32.131) ; C23.1@39.116,50.33 v1(39.116,51.308) ; C29.1@41.021,24.168 v1(41.021,25.146) ; C21.1@41.021,43.345 v1(41.021,44.323) ; v1(43.392,43.307) C26.2@44.786,43.307 ; C33.2@43.815,10.205 v1(43.815,11.599) ; C36.1@43.945,68.834 v1(45.339,68.834) ; C34.1@43.945,71.374 v1(45.339,71.374)
  Bottom Layer w0.508: v1(41.021,25.146) 41.021,29.54 J7.5@49.08,29.54 ; v1(45.339,68.834) 45.339,66.54 J6.5@49.08,66.54
  other v1: 43.18,14.478 44.45,14.478 43.18,15.748 44.45,15.748 43.434,38.1 44.704,38.1 43.434,39.37 44.704,39.37 3.175,65.405 4.445,65.405 3.175,66.675 4.445,66.675 29.845,70.739 31.115,70.739 29.845,72.009 31.115,72.009
  other v2: 17.399,24.384 18.415,24.384 19.431,24.384 17.399,25.4 18.415,25.4 19.431,25.4 17.399,26.416 18.415,26.416 19.431,26.416 19.939,47.879 20.955,47.879 21.971,47.879 19.939,48.895 20.955,48.895 21.971,48.895 19.939,49.911 20.955,49.911 21.971,49.911 19.05,53.594 23.241,53.594 18.034,54.61 24.257,54.61 20.066,54.864 22.225,54.864 17.145,56.007 19.05,56.007 22.733,56.007 24.638,56.007
IP_3.3A: C12.2 C13.2 L2.1 U3.31 | length 14.2
  Top Layer w0.229: C13.2@15.367,58.585 16.091,58.585 16.383,58.293 16.383,55.372 19.955,51.8 U3.31@19.955,51.045
  Top Layer w0.508: L2.1@12.865,61.087 12.865,59.655 C12.2@13.335,59.185 14.767,59.185 C13.2@15.367,58.585
IP_3.3V: C9.2 C14.2 C15.2 L1.2 L2.2 R12.1 R13.1 R18.2 R19.2 R20.2 U3.13 | length 15.3
  Top Layer w0.229: v1(20.955,44.323) 21.155,44.523 U3.13@21.155,46.745
  Top Layer w0.508: C15.2@8.763,58.585 9.363,59.185 C14.2@10.795,59.185 11.265,59.655 L2.2@11.265,61.087 v1(10.16,61.087) ; v1(8.89,62.357) R12.1@8.89,63.335 R13.1@10.287,63.335 ; v1(18.161,40.767) R18.2@18.161,41.745 ; v1(19.558,40.767) R19.2@19.558,41.745 ; C9.2@20.955,43.345 v1(20.955,44.323) ; L1.2@22.352,43.345 v1(22.352,44.323) ; R20.2@27.47,50.165 v1(28.448,50.165)
ISET: R23.1 U3.25 | length 4.8
  Top Layer w0.152: U3.25@22.355,51.045 22.355,51.819 23.495,52.959 R23.1@25.87,52.959
LED1: LD3.2 U1.1 | length 7
  Top Layer w0.152: U1.1@21.415,29.625 21.415,30.432 22.225,31.242 22.225,33.782 22.606,34.163 LD3.2@24.6,34.163
LED2: LD4.2 U1.2 | length 8.8
  Top Layer w0.152: U1.2@21.015,29.625 21.015,30.54 21.844,31.369 21.844,35.179 22.225,35.56 LD4.2@24.6,35.56
MDC: U1.27 U3.22 | length 41.2
  Top Layer w0.152: v2(11.43,24.13) 12.7,24.13 12.97,24.4 U1.27@14.19,24.4 ; U3.22@23.105,49.495 v2(24.257,49.495)
  Bottom Layer w0.152: v2(11.43,24.13) 11.176,24.384 11.176,29.464 11.811,30.099 21.209,30.099 22.225,31.115 22.225,36.449 25.146,39.37 25.146,48.606 v2(24.257,49.495)
MDI_R_N: P1.R8 R17.1 | length 23.8
  Top Layer w0.229: P1.R8@15.055,68.72 15.055,69.654 14.732,69.977 13.843,69.977 13.335,69.469 13.335,66.04 ccw(c13.564,66.04) 13.564,65.811 13.906,65.811 cw(c13.906,65.583) 14.135,65.583 cw(c13.906,65.583) 13.906,65.354 13.564,65.354 ccw(c13.564,65.126) 13.335,65.126 13.335,64.897 13.335,64.77 13.335,64.389 16.129,61.595 23.145,61.595 23.876,60.864 23.876,59.093 R17.1@24.384,58.585
MDI_R_P: P1.R7 R16.1 | length 23.8
  Top Layer w0.229: P1.R7@16.325,71.26 15.423,70.358 13.685,70.358 12.954,69.627 12.954,64.231 15.971,61.214 22.987,61.214 23.495,60.706 23.495,59.093 R16.1@22.987,58.585
MDI_T_N: P1.R2 R15.1 | length 22.2
  Top Layer w0.229: R15.1@18.796,58.585 v2(18.796,59.563)
  Bottom Layer w0.229: v2(18.796,59.563) 18.288,59.055 18.288,58.674 18.669,58.293 23.495,58.293 24.13,58.928 24.13,63.881 24.13,64.389 ccw(c23.901,64.389) 23.901,64.618 23.7,64.618 cw(c23.7,64.846) 23.471,64.846 cw(c23.7,64.846) 23.7,65.075 23.901,65.075 ccw(c23.901,65.303) 24.13,65.303 ccw(c23.901,65.303) 23.901,65.532 23.7,65.532 cw(c23.7,65.761) 23.471,65.761 cw(c23.7,65.761) 23.7,65.989 23.901,65.989 ccw(c23.901,66.218) 24.13,66.218 24.13,66.446 24.13,66.675 24.13,69.088 23.876,69.342 23.297,69.342 P1.R2@22.675,68.72
MDI_T_P: P1.R1 R14.1 | length 22.2
  Top Layer w0.229: R14.1@17.399,58.585 v2(17.399,59.563)
  Bottom Layer w0.229: v2(17.399,59.563) 17.907,59.055 17.907,58.516 18.511,57.912 23.653,57.912 24.511,58.77 24.511,69.246 23.945,69.812 P1.R1@23.945,71.26
MDIO: R20.1 U1.26 U3.23 | length 42.4
  Top Layer w0.152: v2(11.938,24.638) 12.7,24.638 12.862,24.8 U1.26@14.19,24.8 ; U3.23@23.105,49.895 23.86,49.895 24.13,50.165 v2(24.892,50.165) R20.1@25.87,50.165
  Bottom Layer w0.152: v2(11.938,24.638) 11.557,25.019 11.557,29.337 11.938,29.718 21.336,29.718 22.606,30.988 22.606,36.322 25.527,39.243 25.527,48.768 24.892,49.403 v2(24.892,50.165)
NetC7_1: C7.1 R10.1 SW1.1 U2.3 | length 52.6
  Top Layer w0.152: U2.3@32.7,43.645 32.55,43.795 R10.1@32.55,45.72 C7.1@32.55,47.117 32.55,52.743 33.02,53.213 39.497,53.213 39.878,53.594 39.878,63.119 40.386,63.627 45.974,63.627 46.355,64.008 46.355,80.055 SW1.1@48.75,82.45
NetC16_2: C16.2 C17.2 U3.28 | length 7.7
  Top Layer w0.229: v1(20.193,56.007) 21.155,55.045 U3.28@21.155,51.045
  Top Layer w0.508: v1(20.193,56.007) C16.2@20.193,56.985 C17.2@21.59,56.985
NetC18_2: C18.2 P1.R3 | length 6.3
  Top Layer w0.508: C18.2@21.405,64.935 P1.R3@21.405,71.26
NetC20_1: C20.1 U4.1 | length 3.5
  Top Layer w0.152: U4.1@39.613,45.619 39.613,47.703 C20.1@40.64,48.73
NetC20_2: C20.2 U4.3 | length 10
  Top Layer w0.152: U4.3@38.313,45.619 38.313,47.838 38.354,47.879 38.354,51.689 38.735,52.07 40.259,52.07 40.64,51.689 C20.2@40.64,50.33
NetC23_2: C23.2 U4.2 | length 3.2
  Top Layer w0.152: U4.2@38.963,45.619 38.963,47.726 39.116,47.879 C23.2@39.116,48.73
NetC24_1: C24.1 U4.4 | length 3.1
  Top Layer w0.152: C24.1@37.592,48.73 37.592,47.879 37.663,47.808 U4.4@37.663,45.619
NetC24_2: C24.2 U4.5 | length 5.1
  Top Layer w0.152: U4.5@37.013,45.619 37.013,47.696 36.83,47.879 36.83,49.568 C24.2@37.592,50.33
NetC25_2: C25.2 U4.6 | length 3.2
  Top Layer w0.152: C25.2@36.068,48.73 36.068,47.879 36.363,47.584 U4.6@36.363,45.619
NetC28_1: C28.1 U6.1 | length 3.5
  Top Layer w0.152: U6.1@39.613,26.443 39.613,28.526 C28.1@40.64,29.553
NetC28_2: C28.2 U6.3 | length 10
  Top Layer w0.152: U6.3@38.313,26.443 38.313,28.661 38.354,28.702 38.354,32.512 38.735,32.893 40.259,32.893 40.64,32.512 C28.2@40.64,31.153
NetC30_2: C30.2 U6.2 | length 3.2
  Top Layer w0.152: U6.2@38.963,26.443 38.963,28.549 39.116,28.702 C30.2@39.116,29.553
NetC31_1: C31.1 U6.4 | length 3.1
  Top Layer w0.152: C31.1@37.592,29.553 37.592,28.702 37.663,28.631 U6.4@37.663,26.443
NetC31_2: C31.2 U6.5 | length 5.1
  Top Layer w0.152: U6.5@37.013,26.443 37.013,28.519 36.83,28.702 36.83,30.391 C31.2@37.592,31.153
NetC32_2: C32.2 U6.6 | length 3.2
  Top Layer w0.152: C32.2@36.068,29.553 36.068,28.702 36.363,28.407 U6.6@36.363,26.443
NetJ6_2: J6.2 R28.2 | length 3.9
  Top Layer w0.152: R28.2@45.25,58.039 45.441,58.23 J6.2@49.08,58.23
NetJ6_3: J6.3 R30.2 | length 3.9
  Top Layer w0.152: R30.2@45.25,61.087 45.337,61 J6.3@49.08,61
NetJ6_7: J6.7 R29.2 | length 6.7
  Top Layer w0.152: R29.2@45.25,59.563 45.302,59.615 J6.7@51.92,59.615
NetJ6_8: J6.8 R31.2 | length 6.8
  Top Layer w0.152: R31.2@45.25,62.611 45.476,62.385 J6.8@51.92,62.385
NetJ7_2: J7.2 R32.2 | length 3.9
  Top Layer w0.152: R32.2@45.25,21.039 45.441,21.23 J7.2@49.08,21.23
NetJ7_3: J7.3 R34.2 | length 3.9
  Top Layer w0.152: R34.2@45.25,24.087 45.337,24 J7.3@49.08,24
NetJ7_7: J7.7 R33.2 | length 6.7
  Top Layer w0.152: R33.2@45.25,22.563 45.302,22.615 J7.7@51.92,22.615
NetJ7_8: J7.8 R35.2 | length 6.8
  Top Layer w0.152: R35.2@45.25,25.611 45.476,25.385 J7.8@51.92,25.385
NetLD1_1: LD1.1 R6.1 | length 2.2
  Top Layer w0.152: R6.1@5.461,12.23 LD1.1@5.461,14.44
NetLD2_1: LD2.1 R7.1 | length 2.2
  Top Layer w0.152: R7.1@4.064,12.23 LD2.1@4.064,14.44
NetLD3_1: LD3.1 R8.1 | length 2.2
  Top Layer w0.152: LD3.1@26.2,34.163 R8.1@28.41,34.163
NetLD4_1: LD4.1 R11.1 | length 2.2
  Top Layer w0.152: LD4.1@26.2,35.56 R11.1@28.41,35.56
